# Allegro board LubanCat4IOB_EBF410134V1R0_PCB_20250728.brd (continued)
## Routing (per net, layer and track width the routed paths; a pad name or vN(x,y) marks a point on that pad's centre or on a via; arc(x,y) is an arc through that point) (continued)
N18315834: length 3.4
  BOTTOM w0.203: U33.20 46.17,69.22 45.47,69.93 45.47,70.48 45.21,70.74 C180.1
N18315837: length 2.8
  BOTTOM w0.203: U33.19 46.12,68.78 45.17,69.72 C181.1
N18315840: length 2.5
  BOTTOM w0.203: U33.10 49.22,63.94 C182.1
N18319040: length 5.1
  TOP w0.203: P1.1 58.22,87.22 58.22,85.26 C184.1 57.91,84.95 R199.1 R196.2
N18319047: length 5.2
  TOP w0.203: R202.1 R201.1 58.93,84.95 C184.2 58.57,85.31 58.57,87.17 P1.2
N18319296: length 2
  TOP w0.254: R196.1 C183.1 R192.1
N18351323: length 17.7
  BOTTOM w0.305: R76.2 64.26,18.54 64.64,18.16 64.64,16.76 62.48,14.6 62.48,11.43 63.37,10.54 66.8,10.54 67.44,11.17 67.44,12.75 67.74,13.05 J14.3
N18351325: length 16.1
  BOTTOM w0.305: R77.2 65.66,18.54 65.15,18.03 65.15,16.55 62.99,14.39 62.99,11.64 63.63,11 66.57,11 66.93,11.35 66.93,12.75 66.62,13.05 J14.4
N18351329: length 15.2
  BOTTOM w0.305: J14.2 73.99,13.05 74.47,12.57 74.47,10.96 74.12,10.61 71.94,10.61 71.27,11.28 71.27,17.8 72.01,18.54 R75.2
N18351335: length 16.7
  BOTTOM w0.305: R74.2 70.61,18.41 70.82,18.21 70.82,10.97 71.63,10.15 74.31,10.15 74.93,10.78 74.93,12.57 75.41,13.05 J14.1
N18375618: length 1.9
  TOP w0.152: v1(11.1,17.65) 11.18,17.65 11.18,17.66 D3.1
  BOTTOM w0.152: Q4.3 11.84,17.66 11.18,17.66 11.18,17.65 v1(11.1,17.65)
N18375621: length 1.7
  TOP w0.152: D3.2 R35.2
N18375775: length 4.7
  BOTTOM w0.152: R38.2 R41.1 12.44,18.55 12.89,18.1 Q4.1
N18376132: length 2.5
  TOP w0.152: D4.1 v1(13.72,17.66)
  BOTTOM w0.152: Q5.3 15.14,17.66 v1(13.72,17.66)
N18376134: length 1.7
  TOP w0.152: D4.2 R36.2
N18376144: length 4.7
  BOTTOM w0.152: R39.2 R42.1 16.19,18.6 Q5.1
N18437233: length 2.3
  BOTTOM w0.152: U38.3 26.73,91 26.92,90.8 26.92,90.17 27.05,90.04 R235.1
N18438798: length 4.5
  BOTTOM w0.152: R236.2 R237.1 22.23,90.04 23.18,91 U38.4
N18458541: length 8.2
  TOP w0.381: SW4.4 v1(3.43,33.24) SW4.3
  BOTTOM w0.254: R31.1 R30.1 C44.1 Z6.2 3.46,33.26 v1(3.43,33.24)
N18458605: length 8.1
  TOP w0.381: SW5.4 v1(3.49,37.62) SW5.3
  BOTTOM w0.203: R33.1 R32.1 5.22,37.61 C45.1 Z7.2 3.52,37.6 v1(3.49,37.62)
N18463759: length 2.6
  TOP w0.152: LED1.1 9.43,17.56 v1(7.79,17.56)
  BOTTOM w0.152: Q3.3 v1(7.79,17.56)
N18463775: length 1.7
  TOP w0.152: LED1.2 R34.2
N18463803: length 4.7
  BOTTOM w0.152: Q3.1 9.59,18.1 9.14,18.55 R40.1 R37.2
N18464833: length 3.1
  TOP w0.152: U7.3 v1(12.63,10.02)
  BOTTOM w0.152: R45.2 R43.2 12.57,10.08 v1(12.63,10.02)
N18464854: length 4.1
  TOP w0.381: U7.2 v1(11.36,10.02)
  BOTTOM w0.254: C47.1 11.36,10.86 v1(11.36,10.02)
  BOTTOM w0.381: C47.1 C48.1 R44.2
N18479746: length 6.1
  BOTTOM w0.508: R217.1 42.93,101.09 41.62,99.79 J26.1
N18479761: length 15.4
  BOTTOM w0.203: Q17.2 38.8,84.7 40.34,86.23 43.18,86.23 43.94,86.99 43.94,87.75 Z10.2 44.08,89.14 44.08,89.71 J26.3 40.1,93.69 J26.5
N18479774: length 18.6
  BOTTOM w0.203: Q16.2 43.54,85.47 45.72,85.47 46.91,86.66 46.91,92.4 46.1,93.22 R206.2 Z9.2 41.9,97.3 J26.2
N18480030: length 10.7
  TOP w0.203: J26.4 39.9,88.98 40.33,89.41 43.35,89.41 44.02,88.74 44.02,84.37 R205.2
N18480910: length 2
  BOTTOM w0.203: R208.1 C188.1 52.44,76.2 R207.2
N18480944: length 4.4
  BOTTOM w0.508: R219.1 50.86,99.82 J27.1
N18528085: length 6.7
  BOTTOM w0.254: J9.6 37.47,14.74 38.1,15.37 R52.2
N18528088: length 7.6
  BOTTOM w0.254: R50.2 45.85,18.16 48.9,15.1 J9.3
N18639472: length 17.6
  BOTTOM w0.203: R212.2 28.82,78.48 28.62,78.69 U34.5 29.82,79.75 30.99,80.92 30.99,83.31 33.4,85.72 33.4,87.65 32.98,88.07 31.27,88.07 30.16,86.97 J28.2
N18639500: length 4.1
  BOTTOM w0.203: R209.2 R212.1 31.61,79.37 32,79.75 U34.4
N18639545: length 5.6
  BOTTOM w0.152: U34.2 32.51,82.29 32.26,82.04 32.26,81.28 32.51,81.02 U34.3 35.3,81.02 C192.1
N18639570: length 2
  BOTTOM w0.203: R204.2 R203.2 31.61,75.44 C185.1
N18639588: length 1
  BOTTOM w0.203: R209.1 C185.2
N18642135: length 6.4
  BOTTOM w0.152: U8.2 3.31,84.76 4.33,85.78 4.33,87.23 C52.1 3.44,88.11 Y1.2
N18642163: length 7
  BOTTOM w0.152: Y1.1 5.45,88.11 C51.1 4.63,87.3 4.63,85.66 3.09,84.11 U8.1
N18642204: length 3.1
  BOTTOM w0.305: U8.8 7.53,84.11 C49.1
  BOTTOM w0.381: C49.1 8.86,84.59 D5.3
N18642319: length 5
  BOTTOM w0.152: R48.1 R47.2 4.45,84.2 5.01,84.76 U8.7
N18645225: length 2.8
  BOTTOM w0.203: Q16.3 41.66,81.78 R211.2 40.86,80.98 R210.2
N18645232: length 2.8
  BOTTOM w0.203: Q17.3 37.85,81.78 R215.2 38.65,80.98 R213.2
N18645288: length 1.9
  BOTTOM w0.203: R213.1 36.96,79.92 C193.2
N18645295: length 1.9
  BOTTOM w0.203: C191.2 42.46,78.19 R210.1
N18645705: length 10.1
  BOTTOM w0.203: R216.2 C195.1 44.38,83.62 41.63,83.62 Q16.1 39.78,83.62 37.82,83.62 Q17.1
N18647092: length 5.5
  BOTTOM w0.203: U34.8 29.77,83.56 32.13,85.92 J28.1
N18656178: length 5.3
  BOTTOM w0.152: U21.4 99.25,101.15 99.06,101.34 97.19,101.34 97.04,101.19 C104.1 97.03,100.07 R124.2
N18804334: length 2.3
  TOP w0.305: J11.2 96.21,19.46 96.43,19.24 R63.2
N18804414: length 2.4
  TOP w0.305: R71.2 88.81,19.11 88.46,19.46 J13.2
N18903114: length 7.1
  TOP w0.381: SW6.3 v1(3.49,39.86) SW6.4
  BOTTOM w0.203: v1(3.49,39.86) 3.58,39.77 Z12.2 C212.1 R239.1

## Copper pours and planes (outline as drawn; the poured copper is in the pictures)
1V05_DVDD_PHY on TOP: 111.25,65.91 113.54,65.91 113.74,65.71 113.74,64.72 113.67,64.64 113.41,64.64 113.23,64.82 113.23,65.07 113.16,65.15 112.01,65.15 111.89,65.02 111.89,62.23 111.76,62.1 111.25,62.1 111.12,62.23 111.12,65.78
1V05_PHY on TOP: 112.27,62.86 112.78,62.86 112.9,62.74 112.9,61.21 112.78,61.09 107.82,61.09 107.7,60.96 107.7,59.94 107.57,59.82 106.17,59.82 106.05,59.94 106.05,61.72 106.17,61.85 112.01,61.85 112.14,61.97 112.14,62.74
1V05_PHY on BOTTOM: 107.7,61.59 109.73,61.59 109.73,59.31 109.6,59.18 106.17,59.18 106.05,59.31 106.05,60.2 106.17,60.32 107.57,60.32 107.7,60.45
3V3_DVDD_PHY on TOP: 110.11,63.63 109.98,63.75 109.98,64.77 109.73,65.02 108.46,65.02 108.08,65.4 108.08,67.69 109.6,69.21 110.49,69.21 110.62,69.34 110.62,71.32 109.68,72.26 108.71,72.26 108.58,72.39 108.58,72.77 108.71,72.9 109.86,72.9 110.49,72.26 112.52,72.26 113.28,73.02 115.7,73.02 115.82,72.9 115.82,72.52 115.7,72.39 113.79,72.39 113.16,71.75 113.16,70.36 113.03,70.23 112.55,70.23 112.42,70.1 112.42,67.64 112.32,67.54 109.3,67.54 108.97,67.21 108.97,66.14 109.19,65.91 110.74,65.91 110.87,65.78 110.87,63.75 110.74,63.63
3V3_DVDD_PHY on BOTTOM: 108.46,73.79 109.22,73.79 109.22,70.86 109.47,70.61 109.47,70.1 109.35,69.98 108.71,69.98 108.46,70.23
3V3_DVDD_PHY on BOTTOM: 110.19,66.24 110.67,66.24 110.74,66.17 110.74,63.83 110.67,63.75 110.26,63.75 110.11,63.91 110.11,66.17
3V3_DVDD_PHY on BOTTOM: 117.09,74.67 117.09,73.15 116.97,73.02 115.82,73.02 115.7,72.9 115.7,72.52 115.57,72.39 114.3,72.39 114.05,72.64 114.05,73.66 114.17,73.79 115.82,73.79 115.95,73.91 115.95,74.61 116.08,74.74 117.02,74.74
3V3_IMAGE0 on TOP: 126.54,91.67 126.62,91.49 126.8,91.41 128.02,91.41 128.2,91.49 128.27,91.67 128.27,93.06 128.2,93.24 128.02,93.32 126.8,93.32 126.62,93.24 126.54,93.06
3V3_IMAGE0 on BOTTOM: 126.87,84.71 126.87,81.94 126.62,81.69 125.7,81.69 125.48,81.46 125.48,80.01 125.6,79.88 127.25,79.88 127.25,79.12 124.33,79.12 124.21,79.25 124.21,83.16 124.43,83.39 125.22,83.39 125.35,83.51 125.35,89.33 125.53,89.51 126.29,89.51 126.47,89.69 126.47,93.09 126.72,93.34 128.96,93.34 129.21,93.09 129.21,91.26 127.91,91.26 127.74,91.08 127.74,88.8 127.46,88.52 126.9,88.52 126.7,88.31 126.7,84.89
3V3_IMAGE1 on TOP: 122.16,68.91 127.15,68.91 127.15,68.1 123.14,68.1 122.89,67.84 122.89,66.9 122.61,66.62 118.8,66.62 118.75,66.67 118.75,67.89 118.77,67.92 121.56,67.92 121.82,68.17 121.82,68.57
3V3_WLAN on TOP: 98.04,50.8 98.04,48.39 97.79,48.13 97.28,48.13 97.16,48 97.16,47.37 97.28,47.24 98.42,47.24 99.19,48 99.19,49.53 99.44,49.78 102.49,49.78 102.62,49.91 102.62,50.67 102.36,50.93 98.17,50.93
3V3_WLAN on BOTTOM: 95.76,46.23 95.76,47.62 95.89,47.75 98.42,47.75 98.55,47.62 98.55,46.35 98.42,46.23
5V0_IMAGE0 on TOP: 126.92,86.49 127,86.31 127.18,86.23 127.94,86.23 128.12,86.31 128.19,86.49 128.19,87.58 128.12,87.76 127.94,87.83 127.18,87.83 127,87.76 126.92,87.58
5V0_IMAGE0 on BOTTOM: 127.13,84.71 127.13,81.53 127,81.41 125.86,81.41 125.86,80.14 127.25,80.14 127.25,80.39 128.02,81.15 128.02,85.65 128.3,85.93 129.16,85.93 129.16,87.91 127.2,87.91 126.9,87.6 126.9,84.94
5V0_IMAGE1 on TOP: 127.13,67.94 127.25,67.82 127.25,65.78 127.13,65.66 125.6,65.66 125.48,65.53 125.48,62.86 123.44,60.83 118.75,60.83 118.75,62.1 123.44,62.1 124.59,63.24 124.59,67.69 124.84,67.94
GND on TOP: 115.67,44.5 109.14,44.5 105.33,40.69 105.33,31.21 105.66,30.88 110.87,30.88 111.23,31.23 111.23,37.59 111.79,38.15 115.85,38.15 116.1,38.4 116.1,44.07
GND on TOP: 124.33,23.11 127,23.11 127.25,22.86 127.25,21.59 127,21.33 124.33,21.33 124.08,21.59 124.08,22.86
GND on TOP: 124.21,42.67 124.21,39.37 124.33,39.24 127.25,39.24 127.76,38.73 128.78,38.73 128.91,38.61 128.91,36.57 129.03,36.45 129.54,36.45 129.67,36.57 129.67,38.61 129.79,38.73 130.56,38.73 131.06,39.24 131.7,39.24 131.83,39.37 131.83,39.88 131.7,40 131.06,40 130.56,39.5 127.89,39.5 127.76,39.62 127.76,40.38 127.64,40.51 126.24,40.51 126.11,40.64 126.11,42.67 125.98,42.8 124.33,42.8
GND on BOTTOM: 106.17,74.04 109.09,74.04 109.22,74.17 109.22,75.44 109.09,75.56 105.54,75.56 105.28,75.31 105.28,74.93
GND on BOTTOM: 84.33,100.46 84.33,98.8 84.45,98.68 86.36,98.68 86.49,98.55 86.49,97.28 86.61,97.15 87.12,97.15 87.25,97.28 87.25,98.55 87.38,98.68 90.93,98.68 91.06,98.8 91.06,100.46 90.93,100.58 89.79,100.58 89.66,100.46 89.66,99.57 89.53,99.44 87.38,99.44 87.25,99.57 87.25,100.46 87.12,100.58 86.61,100.58 86.49,100.46 86.49,99.57 86.36,99.44 85.34,99.44 85.22,99.57 85.22,100.46 85.09,100.58 84.45,100.58
GND on BOTTOM: 113.79,35.05 113.79,33.78 113.92,33.65 116.97,33.65 117.09,33.78 117.09,35.05 116.97,35.18 113.92,35.18
GND on BOTTOM: 113.67,32.51 114.05,32.51 114.17,32.38 114.17,30.99 114.05,30.86 113.67,30.86 113.54,30.99 113.54,32.38
GND on BOTTOM: 60.07,46.99 62.36,46.99 62.48,46.86 62.48,45.34 62.36,45.21 60.07,45.21 59.94,45.34 59.94,46.86
GND on BOTTOM: 67.82,46.99 69.85,46.99 69.98,46.86 69.98,45.34 69.85,45.21 67.69,45.21 67.56,45.34 67.56,46.73
GND on BOTTOM: 3,7.51 1.24,8.24 0.51,10 0.51,100 1.24,101.76 3,102.49 130,102.49 131.76,101.76 132.49,100 132.49,10 131.76,8.24 130,7.51 ; 120 cut-outs
GND on BOTTOM: 117.47,73.79 118.62,73.79 119.13,73.28 119.13,71.63 119,71.5 118.36,71.5 118.24,71.63 118.24,72.26 117.35,73.15 117.35,73.66
GND on BOTTOM: 106.17,58.93 109.98,58.93 110.11,58.8 110.11,58.42 109.98,58.29 106.17,58.29 106.05,58.42 106.05,58.8
GND on BOTTOM: 97.66,100.46 97.66,98.8 97.79,98.68 99.69,98.68 99.82,98.55 99.82,97.28 99.95,97.15 100.46,97.15 100.58,97.28 100.58,98.55 100.71,98.68 104.27,98.68 104.39,98.8 104.39,100.46 104.27,100.58 103.12,100.58 103,100.46 103,99.57 102.87,99.44 100.71,99.44 100.58,99.57 100.58,100.46 100.46,100.58 99.95,100.58 99.82,100.46 99.82,99.57 99.69,99.44 98.68,99.44 98.55,99.57 98.55,100.46 98.42,100.58 97.79,100.58
GND on BOTTOM, ART03: 115.67,44.5 109.14,44.5 105.26,40.61 105.26,31.06 105.51,30.81 110.92,30.81 111.3,31.19 111.3,37.67 111.79,38.15 115.85,38.15 116.1,38.4 116.1,44.07
GND on GND02: 132.49,10 131.76,8.24 130,7.51 3,7.51 1.24,8.24 0.51,10 0.51,100 1.24,101.76 3,102.49 130,102.49 131.76,101.76 132.49,100
GND on ART03: 112.19,30.3 112.19,37.06 112.85,37.72 116.18,37.72 116.59,38.12 116.59,40.26 117.2,40.87 130,40.87 130.78,40.08 130.78,37.95 130.15,37.31 130.15,32.26 129.39,31.49 126.19,31.49 125.35,32.33 116.97,32.33 114.63,30 112.5,30
GND on ART03: 16.51,81.86 17.37,81 53.98,81 55.83,82.85 55.83,84.89 59.51,88.57 64.11,88.57 65.15,89.61 65.15,91.74 64.69,92.2 61.44,92.2 60.63,91.39 58.93,91.39 56.08,88.54 48.56,88.54 42.88,82.85 16.97,82.85 16.87,82.96 16.51,82.6
GND on ART03: 31.19,55.09 31.19,52.22 30.45,51.48 17.83,51.48 17.27,52.04 17.27,64.87 19.13,66.72 21.79,66.72 26.19,71.12 29.39,71.12 30.48,72.21 30.48,77.32 31.88,78.71 58.47,78.71 60.22,80.47 65.58,80.47 65.94,80.11 65.94,78.41 65.74,78.21 59.54,78.21 57.71,76.38 33.45,76.38 32.79,75.72 32.79,72.08 34.62,70.26 34.62,68.35 34.29,68.02 27.23,68.02 26.57,67.36 26.57,62.51 25.93,61.87 24.84,61.87 22.86,63.85 21.13,63.85 20.42,64.57 18.92,64.57 18.64,64.29 18.64,63.91 19.25,63.3 19.25,59.84 23.77,55.32 30.96,55.32
GND on ART03: 128.14,93.67 124.69,97.13 45.47,97.13 44.4,98.2 36.42,98.2 36.42,102.49 130,102.49 131.76,101.76 132.49,100 132.49,93.78 132.38,93.67
GND on ART03: 9.27,82.75 9.27,83.69 16.84,91.26 32.26,91.26 38.18,97.18 120.45,97.18 123.19,94.44 123.19,83.72 121.67,82.19 113.84,82.19 113.59,82.45 107.62,82.45 105.44,84.63 79.04,84.63 78.49,85.19 78.49,91.85 76.99,93.34 68.99,93.34 68.81,93.17 61.04,93.17 60.15,92.28 57,92.28 56.21,93.06 50.57,93.06 49.83,92.33 44.96,92.33 44.12,93.17 41.58,93.17 40.74,92.33 39.88,92.33 35.66,88.11 35.08,88.11 34.49,88.7 28.55,88.7 27.97,88.11 23.52,88.11 19.96,84.56 12.42,84.56 10.77,82.9 10.77,82.68 9.35,82.68
GND on ART03: 6.15,7.51 6.15,14.43 6.88,15.16 7.37,15.16 7.37,15.11 8.1,14.38 8.69,14.38 9.35,13.71 17.22,13.71 17.88,14.38 104.44,14.38 104.78,14.71 105.46,14.71 107.34,16.59 115.75,16.59 116.33,17.17 123.95,17.17 124.31,17.52 124.31,18.67 124.79,19.15 128.42,19.15 130.38,21.11 130.38,27.94 131.32,28.88 131.32,60.53 132.28,61.49 132.49,61.49 132.49,10 131.76,8.24 130,7.51
GND on ART03: 70.94,47.88 98.78,47.88 99.62,47.04 99.62,41.73 98.98,41.1 62.26,41.1 62.05,41.3 62.05,44.37 62.84,45.16 65.07,45.16 65.74,45.82 69.6,45.82 70.59,46.81 70.59,47.52
GND on ART03: 3,7.51 1.24,8.24 0.51,10 0.51,100 1.24,101.76 3,102.49 38.18,102.49 38.18,98.17 31.34,91.34 14.83,91.34 7.32,83.82 7.32,30.1 6.83,30.1 6.38,30.56 6.38,41.07 3.61,43.84 3.61,52.02 3.52,52.11 3.73,52.32 3.73,79.12 3.02,79.83 2.51,79.83 1.42,78.74 1.42,52.73 1.5,52.65 1.5,41.53 4.37,38.66 4.37,18.08 7.32,15.14 7.32,7.51 ; 1 cut-out
GND on ART03: 59.69,79.91 58.8,79.91 58.5,80.21 58.5,83.21 61.01,85.72 70.84,85.72 71.96,84.61 79.38,84.61 79.81,85.04 79.81,86.21 78.97,87.04 59.21,87.04 57.3,85.14 57.3,78.56 57.68,78.18 58.45,78.18 59.69,79.42
GND on ART03: 13.31,37.39 28.5,37.39 29.06,36.83 47.8,36.83 48.54,36.09 55.47,36.09 56.34,36.96 58.85,36.96 60.53,38.63 101.7,38.63 101.96,38.38 101.96,35.15 101.57,34.77 62.1,34.77 60.63,33.3 60.63,30.78 59.99,30.15 29.97,30.15 28.93,29.11 28.93,24.21 29.29,23.85 30.45,23.85 30.73,23.57 30.73,21.39 30.53,21.18 11.86,21.18 10.85,22.2 10.85,29.08 12.9,31.14 12.9,36.98
GND on ART03: 124.89,64.92 108.2,64.92 107.82,64.54 95.53,64.54 95.07,64.08 95.07,61.31 94.89,61.14 94.89,60.65 95.28,60.27 104.37,60.27 106.73,57.91 121.69,57.91 122.89,56.72 123.9,56.72 124.87,55.75 124.87,52.81 125.32,52.35 126.97,52.35 127.89,53.26 127.89,57.2 126.7,58.39 126.11,58.39 125.22,59.28 125.22,64.59
GND on ART03: 7.11,31.24 8.84,31.24 11.2,33.6 11.2,65.78 18.92,73.51 19.48,73.51 21.84,75.87 21.84,76.81 22.71,77.67 22.71,77.72 23.95,77.72 24.54,77.14 24.54,73.48 26.31,71.7 26.31,70.51 26.57,70.26 29.97,70.26 30.53,70.81 30.53,78.46 29.74,79.25 17.68,79.25 17.65,79.22 17.42,79.45 17.42,83.36 16.69,84.1 9.17,84.1 7.11,82.04
GND on PWR04: 3,7.51 1.24,8.24 0.51,10 0.51,100 1.24,101.76 3,102.49 130,102.49 131.76,101.76 132.49,100 132.49,10 131.76,8.24 130,7.51 ; 2 cut-outs
GND on GND05: 130,102.49 131.76,101.76 132.49,100 132.49,10 131.76,8.24 130,7.51 3,7.51 1.24,8.24 0.51,10 0.51,100 1.24,101.76 3,102.49
VBUS_TYPEC on TOP: 26.42,99.69 26.42,98.42 26.54,98.3 27.18,98.3 27.3,98.42 27.3,99.69 27.18,99.82 26.54,99.82
VBUS_TYPEC on BOTTOM: 25.4,92.58 27.18,92.58 27.3,92.45 29.84,92.45 29.84,98.55 28.7,99.69 26.54,99.69 26.42,99.57 26.42,96.26 27.3,95.38 27.3,93.34 27.18,93.22 25.4,93.22
VCC3V3_SYS on TOP: 126.54,94.06 126.62,93.88 126.8,93.8 128.02,93.8 128.2,93.88 128.27,94.06 128.27,95.17 128.2,95.35 128.02,95.43 126.8,95.43 126.62,95.35 126.54,95.17
VCC3V3_SYS on TOP: 3.56,45.59 3.56,44.09 3.84,43.81 8.28,43.81 8.59,43.51 8.59,41.5 8.99,41.1 19.38,41.1 19.63,41.35 19.63,42.73 19.38,42.99 10.81,42.99 10.52,43.28 10.52,46.15 10.19,46.48 7.49,46.48 7.37,46.35 7.37,45.85 7.14,45.62 3.58,45.62
VCC3V3_SYS on TOP: 118.75,65.4 119.38,65.4 119.76,65.02 120.78,65.02 120.9,64.9 120.9,64.01 121.03,63.88 122.05,63.88 122.17,64.01 124.21,64.01 124.33,63.88 124.33,63.37 123.98,63.02 119.91,63.02 119.63,63.3 119.63,64.01 119.51,64.13 118.75,64.13
VCC3V3_SYS on BOTTOM: 126.75,95.38 127.13,95.38 127.64,94.87 128.91,94.87 129.03,94.74 129.03,93.98 128.91,93.85 126.75,93.85 126.62,93.98 126.62,95.25
VCC3V3_SYS on BOTTOM: 6.35,46.61 6.35,43.94 6.48,43.81 8.38,43.81 8.51,43.94 8.51,46.61 8.38,46.73 6.48,46.73
VCC3V3_SYS on BOTTOM: 20.83,41.27 20.7,41.15 19.18,41.15 19.05,41.27 19.05,42.8 19.18,42.92 20.7,42.92 20.83,42.8
VCC3V3_SYS on ART03: 5.21,44.32 5.21,70.48 5.59,70.86 5.59,82.8 7.62,84.83 7.62,84.86 15.47,92.71 29.21,92.71 30.23,93.72 33.07,93.72 37.72,98.37 37.72,100.96 38.35,101.6 123.37,101.6 125.35,99.62 126.85,99.62 129.57,96.9 129.92,96.9 132,94.82 132,60.73 131.72,60.45 122.81,60.45 122.56,60.7 122.56,64.01 122.81,64.26 127.74,64.26 129.95,66.47 129.95,82.85 129.62,83.18 127.13,83.18 125.98,84.33 125.98,89.6 125.09,90.49 125.09,94.49 124.33,94.49 124.21,94.36 95.63,94.36 93.6,96.39 50.55,96.39 49.21,95.06 40.2,95.06 34.92,89.79 23.24,89.79 22.8,89.34 15.56,89.34 9.04,82.83 9.04,44.22 8.64,43.81 5.71,43.81
VCC5V0_SYS on TOP: 118.75,59.56 119.38,59.56 119.89,59.05 120.78,59.05 120.9,58.93 120.9,58.29 121.16,58.04 121.79,58.04 122.17,58.42 122.17,58.8 122.3,58.93 124.21,58.93 124.33,58.8 124.33,58.04 124.21,57.91 122.81,57.91 122.05,57.15 120.02,57.15 119.89,57.28 119.89,58.16 119.76,58.29 118.75,58.29
VCC5V0_SYS on TOP: 127.89,63.63 127.89,64.77 127.76,64.9 126.49,64.9 126.36,64.77 126.36,62.99 126.49,62.86 127.89,62.86 128.02,62.74 128.02,61.85 128.65,61.85 128.65,63.37 128.52,63.5 128.02,63.5
VCC5V0_SYS on TOP: 127.38,89.2 127.46,89.02 127.64,88.95 128.55,88.95 128.73,89.02 128.8,89.2 128.8,90.68 128.73,90.86 128.55,90.93 127.64,90.93 127.46,90.86 127.38,90.68
VCC5V0_SYS on TOP: 3.58,63.68 3.58,57.66 3.81,57.43 6.53,57.43 6.76,57.66 6.76,59.74 6.53,59.97 6.25,59.97 6.07,60.15 6.07,63.68
VCC5V0_SYS on TOP: 127.89,41.53 127.89,42.67 127.76,42.8 126.49,42.8 126.36,42.67 126.36,40.89 126.49,40.77 127.89,40.77 128.02,40.64 128.02,39.75 128.65,39.75 128.65,41.27 128.52,41.4 128.02,41.4
VCC5V0_SYS on TOP: 24.23,30.73 24.23,29.77 24.61,29.39 24.61,24.74 23.62,24.74 23.62,26.01 23.37,26.26 19.25,26.26 18.92,26.59 18.92,30.71 19.28,31.06 23.9,31.06
VCC5V0_SYS on BOTTOM: 22.83,70.38 22.83,71.35 22.25,71.93 22.25,72.82 22.1,72.97 21.34,72.97 21.21,73.1 21.21,73.68 21.34,73.81 22.91,73.81 23.04,73.68 23.04,71.98 23.14,71.88 23.14,71.14 23.29,70.99 23.65,70.99 23.65,70.38
VCC5V0_SYS on BOTTOM: 87.5,101.34 87.5,99.69 89.28,99.69 89.41,99.82 89.41,100.71 89.53,100.84 90.17,100.84 90.3,100.96 90.3,101.34 90.17,101.47 87.63,101.47
VCC5V0_SYS on BOTTOM: 100.84,101.34 100.84,99.69 102.62,99.69 102.74,99.82 102.74,100.71 102.87,100.84 103.5,100.84 103.63,100.96 103.63,101.34 103.5,101.47 100.97,101.47
VCC5V0_SYS on BOTTOM: 20.19,49.27 24.38,49.27 24.51,49.15 24.51,48.51 24.38,48.39 20.19,48.39 20.07,48.51 20.07,49.15
VCC5V0_SYS on BOTTOM: 20.7,30.91 20.7,27.58 20.5,27.38 18.49,27.38 18.49,29.01 18.95,29.01 19.18,29.23 19.18,30.96 19.3,31.09 20.52,31.09
VCC5V0_SYS on BOTTOM: 29.41,81.48 29.51,81.38 29.51,80.82 29.41,80.72 26.87,80.72 26.54,80.39 24.64,80.39 24,81.02 22.35,81.02 22.23,81.15 22.23,82.42 22.35,82.55 23.83,82.55 24.89,81.48
VCC5V0_SYS on BOTTOM: 19.43,92.45 24,92.45 24.13,92.58 24.13,93.22 24,93.34 19.43,93.34 19.3,93.22 19.3,92.58
VCC5V0_SYS on BOTTOM: 3.81,57.66 3.88,57.48 4.06,57.4 6.45,57.4 6.63,57.48 6.71,57.66 6.71,60.88 6.48,61.11 5.56,61.11 5.33,61.34 5.33,62.25 3.63,62.25 3.63,61.62 3.81,61.44
VCC5V0_SYS on BOTTOM: 127.97,88.75 128.04,88.57 128.22,88.49 128.98,88.49 129.16,88.57 129.24,88.75 129.24,90.68 129.16,90.86 128.98,90.93 128.22,90.93 128.04,90.86 127.97,90.68
VCC5V0_SYS on PWR04: 1.52,31.52 1.52,92.89 2.08,93.45 22.86,93.45 23.6,92.71 29.13,92.71 30.2,93.78 33.1,93.78 37.67,98.35 37.67,100.99 38.15,101.48 104.44,101.48 104.78,101.15 104.78,87.55 104.49,87.26 60.5,87.26 57.72,84.48 57.72,79.6 58.29,79.03 63.64,79.03 63.65,79.03 65.98,79.03 67.13,77.89 89.65,77.89 90.24,77.3 96.49,77.3 97.07,76.72 117.25,76.72 118.96,78.43 122.83,78.43 125.67,81.27 125.67,82.65 125.64,82.68 125.64,90.66 126.09,91.11 131.14,91.11 131.48,90.77 131.48,19.4 128.96,16.89 125.45,16.89 123.93,15.37 107.72,15.37 105.59,13.23 37.03,13.23 35.97,12.17 8.86,12.17 2.97,18.06 2.97,30.07
VCC_3V3_S3 on TOP: 22.23,33.02 22.23,46.23 22.1,46.35 19.56,46.35 19.3,46.1 19.3,45.46 19.56,45.21 20.7,45.21 20.95,44.96 20.95,33.02 21.08,32.89 22.1,32.89
VCC_3V3_S3 on TOP: 24.71,31.42 24.94,31.42 25.15,31.22 25.15,29.84 25.83,29.16 26.09,29.16 26.21,29.29 26.21,31.88 26.04,32.05 24.69,32.05 24.51,31.88 24.51,31.62
VCC_3V3_S3 on BOTTOM: 19.43,46.1 19.43,43.43 19.56,43.31 20.7,43.31 20.83,43.43 20.83,46.1 20.7,46.23 19.56,46.23
VCC_3V3_S3 on BOTTOM: 18.67,19.43 18.29,19.05 18.29,10.16 18.41,10.03 18.67,10.03 18.8,10.16 18.8,18.41 19.05,18.67 21.97,18.67 22.23,18.92 22.1,27.78 22.1,31.19 22.35,31.44 25.63,31.44 25.86,31.67 25.86,34.16 25.73,34.29 21.41,34.29 21.18,34.06 21.18,19.61 21.01,19.43
VCC_12V on TOP: 6.99,53.21 6.6,53.59 5.59,53.59 5.59,54.69 5.28,54.99 5.08,54.99 5.08,55.75 5.21,55.88 8.89,55.88 9.27,56.26 9.27,69.87 8.41,70.74 8.41,71.53 7.8,72.13 5.71,72.13 5.59,72.01 5.59,71.25 5.46,71.12 4.95,71.12 4.83,71.25 4.83,74.28 4.2,74.28 3.94,74.55 3.94,76.68 5.33,76.68 5.74,77.09 5.74,82.65 5.31,83.08 3.94,83.08 3.94,85.06 7.59,85.06 8.51,85.98 14.38,85.98 14.38,80.16 14.05,79.83 9.73,79.83 8.94,79.04 8.94,74.78 9.68,74.04 10.03,74.04 11.56,72.52 11.56,53.67 11.1,53.21
VCC_12V on TOP: 78.87,83.82 81.41,83.82 81.53,83.95 81.53,84.07 81.66,84.2 82.55,84.2 82.55,85.22 82.68,85.34 82.93,85.34 83.06,85.47 83.06,86.74 82.93,86.87 78.99,86.87 78.87,86.74
VCC_12V on BOTTOM: 5.33,78.23 5.33,74.42 5.46,74.29 8,74.29 8.13,74.42 8.13,78.1 8,78.23
VCC_12V on ART03: 78.23,86.36 80.26,86.36 80.39,86.49 80.39,87.12 77.47,90.04 67.82,90.04 67.56,89.79 58.42,89.79 54.37,85.74 54.37,82.28 53.87,81.79 25.4,81.79 25.15,81.53 14.5,81.53 14.2,81.84 14.2,82.35 13.97,82.57 12.83,82.57 12.57,82.32 12.57,76.71 12.88,76.4 19.63,76.4 19.96,76.73 19.96,78.87 20.35,79.25 26.62,79.25 27,78.87 45.19,78.87 46.05,78 57.15,78 57.57,78.42 57.57,83.3 60.99,86.71 77.88,86.71
VCCA1V8_CODEC on BOTTOM: 50.37,69.34 52.58,69.34 52.7,69.21 52.7,68.83 52.64,68.77 51.35,68.77 51.26,68.68 50.37,68.68
VDD_3V3 on BOTTOM: 91.57,85.72 92.84,85.72 93.22,85.34 93.22,77.85 93.34,77.72 93.73,77.72 93.85,77.6 93.85,76.83 93.73,76.71 92.46,76.71 92.33,76.83 92.33,84.58 92.2,84.71 91.57,84.71 91.44,84.83 91.44,85.6
VDD_3V3 on BOTTOM: 25.65,43.69 27.43,43.69 27.94,43.18 30.99,43.18 31.24,43.43 31.24,44.45 31.11,44.58 25.65,44.58 25.53,44.45 25.53,43.81
VDD_3V3 on BOTTOM: 62.48,44.45 63.25,45.21 66.17,45.21 66.42,44.96 66.42,42.8 66.55,42.67 66.93,42.67 67.18,42.92 67.18,43.94 67.31,44.07 70.36,44.07 71.75,45.46 74.3,45.46 74.55,45.21 74.55,42.8 74.68,42.67 75.18,42.67 75.31,42.8 75.31,44.58 75.44,44.7 79.76,44.7 80.01,44.45 80.01,42.8 80.14,42.67 80.64,42.67 80.77,42.8 80.77,45.34 80.9,45.46 84.84,45.46 85.22,45.85 86.11,45.85 86.23,45.72 86.23,45.21 86.36,45.08 87.88,45.08 88.01,44.96 88.01,42.8 88.14,42.67 88.65,42.67 88.77,42.8 88.77,44.96 88.9,45.08 92.33,45.08 93.22,45.97 94.11,45.97 94.36,45.72 94.36,44.58 94.61,44.32 95.76,44.32 95.76,45.34 95.12,45.34 95,45.46 95,46.99 94.74,47.24 93.22,47.24 91.95,45.97 86.61,45.97 86.49,46.1 86.49,46.86 86.36,46.99 85.34,46.99 84.33,45.97 70.99,45.97 70.1,45.08 67.56,45.08 66.67,45.97 62.99,45.97 62.1,45.08 60.07,45.08 59.94,45.21 59.94,45.72 59.82,45.85 59.31,45.85 59.18,45.72 59.18,44.45 61.21,42.42 62.36,42.42 62.48,42.54
VDD_3V3 on ART03: 16.26,42.8 16.26,44.32 16.51,44.58 61.59,44.58 61.72,44.45 61.72,42.04 61.59,41.91 30.73,41.91 30.1,42.54 16.51,42.54
VDD_3V3 on PWR04: 73.43,86.61 124.59,86.61 125.15,86.05 125.15,81.36 122.64,78.85 118.69,78.85 116.98,77.14 97.23,77.14 96.6,77.77 90.56,77.77 89.94,78.39 67.44,78.39 66.32,79.51 58.78,79.51 58.16,80.13 58.16,84.14 60.62,86.61 73.42,86.61
VDD_5V on BOTTOM: 60.2,47.24 60.07,47.37 60.07,48.51 60.2,48.64 61.72,48.64 61.85,48.51 61.85,48.39 62.87,47.37 65.02,47.37 65.15,47.5 65.15,49.4 65.28,49.53 65.79,49.53 65.91,49.4 65.91,47.5 66.04,47.37 66.93,47.37 67.56,48 70.36,48 71.5,46.86 72.64,46.86 73.28,47.5 73.28,49.4 73.41,49.53 73.91,49.53 74.04,49.4 74.04,47.24 73.03,46.23 70.99,46.23 69.98,47.24 67.82,47.24 67.31,46.73 62.74,46.73 62.23,47.24
VDD_5V on BOTTOM: 25.65,48.51 27.3,48.51 27.81,48 30.1,48 30.23,48.13 30.23,49.4 30.1,49.53 25.78,49.53 25.65,49.4
VDD_5V on ART03: 45.85,48.64 61.59,48.64 61.72,48.51 61.72,46.99 61.59,46.86 28.96,46.86 28.83,46.99 28.83,49.27 28.96,49.4 30.23,49.4 30.48,49.15 30.48,48.13 30.73,47.88 45.09,47.88
(no net) on TOP: 3,7.51 1.24,8.24 0.51,10 0.51,100 1.24,101.76 3,102.49 130,102.49 131.76,101.76 132.49,100 132.49,10 131.76,8.24 130,7.51 ; 113 cut-outs
5V0_CAM0/1 on TOP: 125.35,60.96 127.25,60.96 127.64,60.58 128.65,60.58 128.65,59.31 127.25,59.31 127.13,59.18 127.13,56.51 127.38,56.26 129.54,56.26 129.67,56.13 129.67,54.74 129.54,54.61 125.73,54.61 125.73,55.88 125.22,56.39 125.22,60.83
5V0_CAM0/1 on BOTTOM: 125.73,45.46 125.73,44.19 125.86,44.07 131.06,44.07 131.44,44.45 131.44,56.01 131.32,56.13 128.14,56.13 128.02,56.01 128.02,54.74 128.14,54.61 129.79,54.61 129.92,54.48 129.92,45.85 129.54,45.46
5V0_CAM2/3 on TOP: 125.35,38.96 127.16,38.96 127.64,38.48 128.65,38.48 128.65,37.21 127.25,37.21 127.13,37.08 127.13,34.51 127.38,34.26 129.54,34.26 129.67,34.13 129.67,32.74 129.54,32.61 125.73,32.61 125.73,37.94 125.6,38.07 125.35,38.07 125.22,38.2 125.22,38.83
5V0_CAM2/3 on BOTTOM: 125.73,23.47 125.73,22.2 125.86,22.07 131.06,22.07 131.83,22.83 131.83,34.03 131.6,34.26 128.14,34.26 127.89,34.01 127.89,32.61 128.14,32.36 130.08,32.36 130.56,31.88 130.56,24.13 129.89,23.47
FAN on BOTTOM: 8.99,64.9 8.99,60.6 9.12,60.48 11.71,60.48 11.71,61.29 10.39,61.29 10.21,61.47 10.21,64.64 9.96,64.9
HUB_3V3 on BOTTOM: 92.46,76.07 93.73,76.07 93.85,75.94 93.85,75.31 93.73,75.18 93.34,75.18 93.22,75.06 93.22,71.5 93.09,71.37 92.46,71.37 92.33,71.5 92.33,72.69 92.2,72.82 92.2,73.02 92.33,73.15 92.33,75.94
MIC1_L on BOTTOM (solid shape): 52.13,84.95 52.2,84.97 52.26,84.95 52.98,84.24 52.2,83.41 51.42,84.24
MIC1_L on BOTTOM (solid shape): 52.01,89.03 52.1,89.01 52.14,88.93 52.14,87.81 50.88,87.77 50.32,88.46
MIC1_L on BOTTOM (solid shape): 52.14,87.77 52.14,86.64 52.1,86.56 52.01,86.55 50.32,87.11 50.88,87.8
MIC1_L on BOTTOM (solid shape): 54.14,97.37 54.14,96.24 54.1,96.16 54.01,96.15 52.32,96.71 52.88,97.4
MIC1_R on BOTTOM (solid shape): 51.6,92.88 51.63,92.96 51.72,92.98 53.52,92.58 52.92,91.87 51.6,91.89
MIC1_R on BOTTOM (solid shape): 52.14,93.67 52.14,92.54 52.1,92.46 52.01,92.45 50.32,93.01 50.88,93.7
MINIPCIE_3V3 on TOP: 106.93,73.02 107.82,73.02 108.08,72.77 108.08,72.39 107.95,72.26 107.7,72.26 107.57,72.13 107.57,69.98 107.44,69.85 106.93,69.85 106.81,69.98 106.81,72.9
MINIPCIE_3V3 on TOP: 90.17,84.58 90.17,82.29 91.82,82.29 92.08,82.04 92.08,81.28 92.2,81.15 94.49,81.15 94.61,81.02 94.61,80.52 94.74,80.39 101.35,80.39 101.47,80.52 101.47,83.18 101.35,83.31 92.08,83.31 91.82,83.56 91.82,84.45 91.69,84.58
MINIPCIE_3V3 on BOTTOM: 99.95,79.73 101.57,78.1 103.5,78.1 103.76,77.85 103.76,73.91 104.78,72.9 106.3,72.9 106.93,72.26 107.95,72.26 108.08,72.39 108.08,72.77 107.95,72.9 107.19,72.9 107.06,73.02 107.06,73.66 106.93,73.79 105.79,73.79 105.16,74.42 105.16,78.99 104.9,79.25 102.41,79.25 101.47,80.19 101.47,82.17 101.35,82.29 100.08,82.29 99.95,82.17
RS485_1_A on TOP (solid shape): 94.29,19.87 93.75,19.34 93.67,19.31 93.58,19.34 93.04,19.87 93.67,20.71
RS485_2_A on TOP (solid shape): 86.54,19.87 86,19.34 85.92,19.31 85.84,19.34 85.3,19.87 85.92,20.71
USB20_VBUS on BOTTOM: 100.84,98.42 104.27,98.42 104.39,98.3 104.39,95.25 104.27,95.12 103.12,95.12 103,95.25 103,97.03 102.87,97.15 100.97,97.15 100.84,97.28
USB30_VBUS on BOTTOM: 87.5,98.42 90.93,98.42 91.06,98.3 91.06,95.12 90.93,94.99 89.79,94.99 89.79,97.03 89.66,97.15 87.5,97.15
N02088 on TOP: 8.41,88.42 8.41,94.54 8.81,94.94 10.54,94.94 10.95,94.54 10.95,90.5 11.25,90.19 11.68,90.19 11.68,88.42
N03633 on TOP: 3.15,52.37 4.06,52.37 4.06,51.69 3.73,51.36 3.73,50.11 3.15,50.11
N03641 on TOP: 4.55,53.31 6.5,53.31 6.5,52.6 5.44,52.6 5.28,52.45 5.28,49.38 5.41,49.25 5.82,49.25 5.84,49.22 5.84,47.83 3.53,47.83 3.53,49.22 3.56,49.25 4.06,49.25 4.14,49.33 4.14,50.95 4.29,51.1 4.29,53.06
N15118646 on BOTTOM: 21.46,44.45 24.26,44.45 24.38,44.32 24.38,43.69 22.35,43.69 22.23,43.56 22.23,41.91 21.34,41.91 21.34,44.32
N15603215 on BOTTOM (solid shape): 109.25,89.83 108.29,89.83 108.11,89.91 108.04,90.09 108.04,91.05 109.3,91.09
N15603215 on BOTTOM (solid shape): 110.79,91.23 110.87,91.05 110.79,90.87 110.11,90.19 109.19,91.05 110.11,91.91
N15603215 on BOTTOM (solid shape): 124.81,91.05 123.89,90.19 123.21,90.87 123.13,91.05 123.21,91.23 123.89,91.91
N15752445 on BOTTOM (solid shape): 60.64,101.24 60.84,101.14 60.88,100.91 60.49,99.63 59.71,100.05 59.75,101.24
N15752445 on BOTTOM (solid shape): 74.25,101.24 74.29,100.05 73.51,99.63 73.12,100.91 73.16,101.14 73.36,101.24
N17466585 on BOTTOM: 107.7,62.36 109.73,62.36 109.75,62.38 109.75,63.96 109.93,64.13 109.93,66.19 109.88,66.24 109.19,66.24 109.12,66.17 109.12,64.92 107.7,63.5
N17592129 on TOP: 82.8,85.09 83.57,85.09 83.57,84.07 83.69,83.95 86.36,83.95 86.51,84.1 86.51,84.61 87.93,84.61 87.93,82.27 86.54,82.27 86.51,82.29 86.51,82.6 86.44,82.68 84.96,82.68 84.71,82.93 83.57,82.93 82.8,83.69
N18211553 on TOP: 3.43,65.78 8.64,65.78 8.69,65.84 8.69,66.6 6.43,66.6 6.22,66.8 6.22,68.2 6.1,68.32 4.95,68.32 4.83,68.45 4.83,70.23 4.7,70.36 4.27,70.36 4.11,70.2 4.11,69.75 3.96,69.59 3.43,69.59 3.3,69.47 3.3,65.91
N18351335 on BOTTOM (solid shape): 76.75,13.05 75.81,12.43 75.28,12.97 75.26,13.05 75.28,13.13 75.81,13.67
N18479761 on BOTTOM (solid shape): 41.2,93.69 41.2,92.69 41.16,92.61 41.07,92.59 39.27,92.99 39.88,93.7
N18479761 on BOTTOM (solid shape): 40.65,93.03 40.69,93.11 40.79,93.13 42.47,92.56 41.91,91.87 40.65,91.91
N18479761 on BOTTOM (solid shape): 43.14,91.87 43.14,90.74 43.1,90.66 43.01,90.65 41.32,91.21 41.88,91.9
N18479774 on BOTTOM (solid shape): 43.06,97.34 43.06,96.24 43.02,96.15 42.93,96.14 41.38,96.73 41.88,97.41

Small or netless copper shapes (teardrops, artwork), in the pictures only: 22 on TOP, 23 on BOTTOM

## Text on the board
Ref Des/Silkscreen Bottom: 20250728 | EBF410134V1R0 | MIPI_DST_TX0 | SIM CARD | CAM0 | CAM2
Ref Des/Silkscreen Top: PWRON | PWR | SYS | IR | USER | NC | TXD | RXD | GND | VO1 | SPK | VO2 | A | EBF410134V1R0 | TXD1 | 20250728 | RXD1 | TXD2 | RXD2 | 2L | 2H | 1L | TX | 1H | USB3.0+USB2.0 HOST | 2A | 2B | 1A | 1B | RS485 | RESET | BOOT | ADC5 | ADC4 | REC | MIC_R | MIC_L | TF CARD | DC IN | RTC | FAN | DEBUG | EAR | RS232 | MIC | CAN | USB2.0 | ETH | TYPE C | MINI PCIE | MIPI_DSI_TX1 | CAM3 | CAM1
BODY_CENTER: C168 | U7 | R72 | R46 | U8 | R55 | J11 | R22 | C20 | C30 | C18 | C83 | C105 | SS4 | SS1 | L7 | L13 | U3 | C21 | R23 | C29 | C64 | C91 | C27 | C66 | U2 | C33 | R15 | C65 | L8 | L12 | C40 | C32 | C34 | C80 | C31 | R9 | C36 | C79 | C37 | L9 | C358 | R11 | C63 | R7 | C359 | R10 | C23 | C11 | L3 | C12 | U10 | D7 | D1 | R12 | D2 | L2 | R13 | C360 | C14 | L14 | D4 | R2 | R4 | C6 | C152 | C164 | R1 | C153 | C165 | C3 | D6 | R37 | D5 | R36 | R33 | J1 | SS3 | SS2 | J8 | Y1 | C170 | R32 | C169 | R31 | R49 | R67 | U9 | R48 | R47 | C68 | C69 | U5 | L5 | C84 | R8 | C22 | R6 | R26 | L11 | C49 | C51 | C45 | C46 | C78 | C76 | C74 | U1 | C48 | C47 | L6 | U4 | C42 | C26 | C25 | C24 | C44 | L1 | L10 | L4 | R17 | R16 | C7 | C8 | C9 | C2 | C5 | C38 | C39 | C16 | C15 | C17 | C90 | C89 | C88 | J7 | J10 | J9 | J6 | MR
DEVICE_TYPE_BOTTOM: C72 | C71 | C70 | R14 | C55 | C58 | C57 | C56 | C81 | C43 | C60 | C59 | C54 | C77 | C61 | C75 | R3 | C13 | C357 | R97 | R96 | R29 | FB1 | R5 | C349 | C348 | C87 | C86 | C108 | C95 | J3 | J2 | R71 | R70 | R35 | R80 | R81 | C310 | C309 | C311 | Q1 | R79 | C306 | C307 | C308 | R77 | R82 | R83 | C314 | J5 | J4 | R51 | R53 | C246 | R85 | R86 | R87 | R88 | R19 | C322 | C328 | C321 | C318 | R40 | C319 | R41 | C324 | C316 | R39 | C329 | C317 | R38 | C327 | C302 | C326 | C158 | C301 | C312 | C133 | C300 | C163 | C180 | C298 | C98 | C299 | C134 | C107 | C336 | C167 | C101 | C115 | C337 | C166 | C99 | C171 | C110 | C304 | C335 | C156 | C305 | C130 | C339 | C127 | C173 | C332 | C172 | C334 | C143 | C296 | C331 | C106 | C154 | C315 | C297 | C343 | C155 | C111 | C198 | C114 | C126 | C140 | C204 | C208 | C145 | C259 | C263 | C142 | C139 | C200 | C206 | C205 | C242 | C194 | C221 | C183 | C195 | C182 | C253 | C262 | C192 | R56 | R59 | C189 | C193 | C256 | R57 | C196 | C220 | C239 | C243 | C261 | R63 | R65 | C278 | C240 | C258 | C230 | C218 | C286 | R62 | C291 | C292 | C257 | R64 | C245 | C219 | C248 | C268 | C271 | C287 | C274 | C254 | C214 | C283 | C269 | C285 | C229 | C238 | C266 | C209 | C222 | C293 | C235 | C265 | C255 | C233 | R21 | C67 | C82 | C73 | D3 | R20 | R24 | R27 | R18 | C50 | C1 | C41 | C19 | C355 | C351 | C94 | C28 | C4 | U6 | C35 | C10 | R98 | C62 | R99 | C138 | C353 | C93 | C356 | C350 | C352 | C354 | R30 | C92 | R25 | C85 | R28 | R95 | R118 | R100 | C362 | C361 | U11 | R94 | R91 | R92 | R93 | R89 | R90 | R44 | R42 | R45 | R43 | R34 | R78 | R84 | C53 | R61 | R60 | C52 | C320 | C323 | C325 | C161 | C347 | C178 | C162 | C160 | C177 | C159 | C346 | C179 | C344 | C123 | C295 | C146 | C345 | C148 | C147 | C151 | C128 | C124 | C174 | C149 | C131 | C132 | C129 | C150 | C122 | C137 | C157 | C97 | C136 | C135 | C96 | C100 | C175 | R73 | C176 | C303 | R75 | C338 | C109 | C113 | R74 | C125 | C102 | C116 | C341 | R76 | C104 | C117 | C340 | C103 | C333 | C112 | C121 | C330 | C144 | C313 | C141 | C119 | C197 | C188 | C342 | C120 | C187 | C186 | C118 | C279 | C288 | C207 | C181 | C202 | C185 | C260 | C251 | C184 | C201 | C211 | C273 | C190 | C284 | C213 | C191 | R54 | C280 | C247 | C199 | C223 | C290 | C203 | C275 | C281 | R58 | C241 | C212 | R66 | C236 | R50 | C237 | R52 | C289 | C252 | C277 | C215 | C249 | C234 | C228 | C231 | C270 | C272 | C226 | C232 | C267 | C225 | C227 | C276 | C294 | R68 | C250 | C210 | R69 | C244 | C264 | C216 | C282 | C224 | C217 | 99 | EBF410133V0R2 | 20241014
DIMENSION: FIGURE | SIZE | 10.0 | 19.685 | 23.622 | 25.591 | 27.559 | 39.37 | 47.244 | 62.992 | 72.047 | 94.5 | 166.142 | 35.433 | 43.307 | 78.701 | 125.984 | 127.953 | 47.244x19.685 | 62.992x23.622 | 66.0x35.0 | 66.929x19.685 | 70.902x15.701 | 74.803x23.622 | 78.74x39.37 | 83.0x35.0 | DRILL CHART: TOP to BOTTOM | ALL UNITS ARE IN MILS | TOLERANCE | +0.0/-0.0 | +3.0/-3.0 | PLATED | NON-PLATED | QTY | 1913 | 2 | 4 | 18 | 13 | 1 | 3 | 6 | 10
